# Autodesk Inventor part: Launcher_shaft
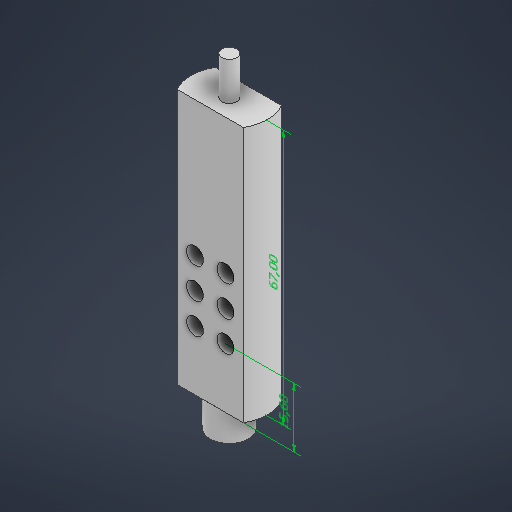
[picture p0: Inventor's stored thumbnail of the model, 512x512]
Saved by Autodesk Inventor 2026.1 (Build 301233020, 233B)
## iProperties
Created: 2025-10
Part Number: Launcher_shaft
Material: Generic
Document SubType Name: Modeling
Designer: Asus
Density: 1 g/cm^3
Appearance: Default
Author: Asus
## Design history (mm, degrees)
node "Annotations"
  node "Linear Dimension 1" dims "d13" = 67 (derived)
  node "Linear Dimension 2" dims "d35" = 15.6 (derived)
sketch "Sketch1"
  geometry: L1 (-2.035, 1.85)-(2.035, 1.85); L2 (2.035, -1.85)-(-2.035, -1.85); L3 (-2.035, 1.85)-(2.035, -1.85); L4 (2.035, 1.85)-(-2.035, -1.85); C1 r 5 at (0, 0); A1 r 2.75 centre (0, 0) between (2.035, -1.85) and (2.035, 1.85); A2 r 2.75 centre (0, 0) between (-2.035, 1.85) and (-2.035, -1.85); 1 further point
  constraints: 8 end point, 4 point on circle, 3 centre point, 2 coincident, 2 midpoint, 1 horizontal, 1 parallel
  dimensions: "d2" = 10 diameter of C1
extrude "Extrusion1" new body sketch "Sketch1" distance "d3" = 8; taper "d4" = 0 deg
sketch "Sketch2"
  geometry: C1 r 10 at (0, 0); 1 further point
  constraints: 1 centre point, 1 coincident
  dimensions: "d10" = 20 diameter of C1
extrude "Extrusion2" join sketch "Sketch2" distance "d5" = 67; taper "d6" = 0 deg
sketch "Sketch3"
  geometry: C1 r 1.95 at (0, 0); 1 further point
  constraints: 1 centre point, 1 coincident
  dimensions: "d7" = 3.9 diameter of C1
extrude "Extrusion3" join sketch "Sketch3" distance "d8" = 10; taper "d9" = 0 deg
sketch "Sketch4"
  geometry: L1 (0, 5)-(8.66, 5); L2 (0, 5)-(-8.66, 5); L3 (-8.66, -5)-(8.66, -5); A1 r 10 centre (0, 0) between (-8.66, -5) and (8.66, -5); A2 r 10 centre (0, 0) between (8.66, 5) and (-8.66, 5); 2 further points
  constraints: 6 end point, 4 point on circle, 2 centre point, 2 horizontal, 1 coincident, 1 parallel, 1 point on line, 1 vertical alignment, 1 other
extrude "Extrusion4" cut sketch "Sketch4" distance "d14" = 67; taper "d15" = 0 deg
sketch "Sketch5"
  geometry: L1 (4.66, -0.4)-(12.66, -0.4); L2 (4.66, -0.4)-(4.66, 67); L3 (17.321, 67)-(0, 67) reference; L4 (4.66, 7.6)-(4.66, 75); L5 (4.66, 15.6)-(4.66, 83); L6 (4.66, 23.6)-(4.66, 91); L7 (4.66, 31.6)-(4.66, 99); L8 (12.66, -0.4)-(12.66, 67); L9 (12.66, 7.6)-(12.66, 75); L10 (12.66, 15.6)-(12.66, 83); L11 (12.66, 23.6)-(12.66, 91); L12 (12.66, 31.6)-(12.66, 99); L13 (8.66, 0)-(0, 0) reference; L14 (13.66, -8)-(3.66, -8) reference; C1 r 2.2 at (4.66, -0.4); C2 r 2.2 at (4.66, 7.6); C3 r 2.2 at (4.66, 15.6); C4 r 2.2 at (4.66, 23.6); C5 r 2.2 at (4.66, 31.6); C6 r 2.2 at (12.66, -0.4); C7 r 2.2 at (12.66, 7.6); C8 r 2.2 at (12.66, 15.6); C9 r 2.2 at (12.66, 23.6); C10 r 2.2 at (12.66, 31.6); 1 further point
  constraints: 22 end point, 10 centre point, 2 horizontal, 2 vertical, 1 collinear, 1 point on line, 35 other
  dimensions: "d24" = 8 distance of L1.start L4.start; "d27" = 8 distance of L1.start L8.start; "d33" = 7.6 distance from line of L14 L1.start
extrude "Extrusion5" cut sketch "Sketch5" distance "d30" = 20.5; taper "d31" = 0 deg
body "Solid1"
node "Sketch Rectangular Pattern1" dims "d24" = 8, "d27" = 8
other parameters: "d0" = 5.5, "d11" = 5.31597 (derived), "d12" = 8.62946 (derived), "d34" = 4.5696 (derived)
